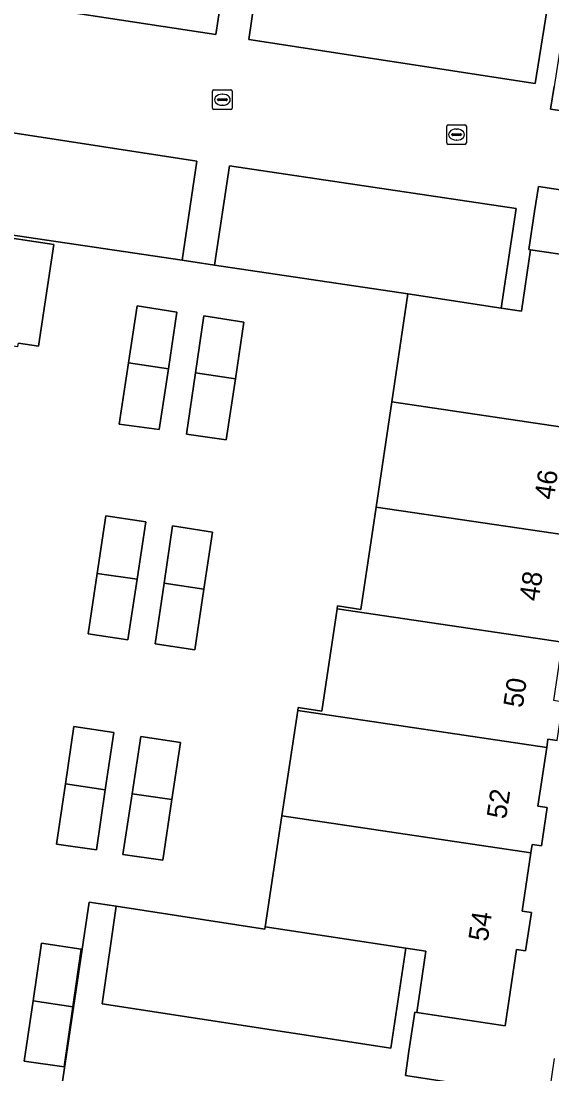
# Model space of a CAD drawing. Extents: x 164148 to 165261, y 382513 to 383432.
# Drawn here: x 164360 to 164386.9, y 382925.3 to 382978.7 of the extents above; entities that cross this region are included whole.
import ezdxf

# ---------------------------------------------------------------- set-up
doc = ezdxf.new("R2010")
doc.units = 0
for name, color, linetype in [('IMGEO_Erf', 7, 'Continuous'), ('IMGEO_Kolk', 7, 'Continuous'), ('IMGEO_Pand', 7, 'Continuous'), ('IMGEO_Pand_nummerreeks', 7, 'Continuous'), ('IMGEO_Parkeervlak_open', 7, 'Continuous'), ('IMGEO_Rijbaan_lokaal_open', 7, 'Continuous')]:
    doc.layers.add(name, color=color, linetype=linetype)

msp = doc.modelspace()

# ---------------------------------------------------------------- linework, layer by layer
at = {"layer": 'IMGEO_Erf'}
for points in [[(164392.466, 382980.616), (164391.885, 382976.741), (164387.391, 382977.422), (164387.359, 382977.427), (164387.033, 382975.364), (164386.852, 382974.222), (164394.057, 382973.175), (164398.318, 383001.938)], [(164393.467, 382969.194), (164386.248, 382970.282), (164386.051, 382969.013), (164385.759, 382967.092), (164385.848, 382967.079), (164390.338, 382966.42)], [(164358.298, 382967.859), (164361.68, 382967.348), (164360.899, 382962.187), (164359.88, 382962.335)], [(164361.351, 382919.771), (164363.474, 382933.973), (164364.842, 382933.776), (164372.377, 382932.608), (164372.394, 382932.721), (164373.238, 382938.355), (164374.038, 382943.697), (164374.061, 382943.851), (164375.257, 382943.667), (164376.031, 382948.861), (164376.053, 382949.005), (164377.241, 382948.828), (164378.014, 382954.022), (164378.809, 382959.364), (164379.624, 382964.842), (164369.817, 382966.301), (164368.18, 382966.545), (164358.321, 382968.013)], [(164387.199, 382942.18), (164386.727, 382942.253), (164386.664, 382941.829), (164386.219, 382938.852), (164386.687, 382938.775), (164386.39, 382936.832), (164385.928, 382936.908), (164385.865, 382936.486), (164385.421, 382933.514), (164385.888, 382933.446), (164385.59, 382931.503), (164385.131, 382931.573), (164384.551, 382927.693), (164380.072, 382928.372), (164379.973, 382928.387), (164379.674, 382926.423), (164379.499, 382925.189), (164386.768, 382924.065), (164387.061, 382926.045)]]:
    msp.add_lwpolyline(points, dxfattribs=at)
for points in [[(164364.994, 382958.226), (164365.463, 382961.338), (164365.9, 382964.242), (164367.918, 382963.916), (164367.484, 382961.04), (164367.019, 382957.953)], [(164369.287, 382963.723), (164371.304, 382963.408), (164370.879, 382960.538), (164370.418, 382957.431), (164368.397, 382957.729), (164368.858, 382960.837)], [(164366.338, 382953.271), (164365.898, 382950.361), (164365.433, 382947.29), (164363.412, 382947.596), (164363.875, 382950.659), (164364.317, 382953.577)], [(164367.265, 382950.158), (164367.697, 382953.069), (164369.715, 382952.755), (164369.286, 382949.859), (164368.83, 382946.783), (164366.81, 382947.09)], [(164364.709, 382942.589), (164364.283, 382939.68), (164363.835, 382936.624), (164361.814, 382936.92), (164362.263, 382939.979), (164362.689, 382942.885)], [(164368.099, 382942.072), (164367.664, 382939.179), (164367.202, 382936.106), (164365.181, 382936.398), (164365.643, 382939.478), (164366.078, 382942.375)], [(164363.066, 382931.596), (164362.64, 382928.668), (164362.197, 382925.618), (164360.174, 382925.912), (164360.619, 382928.967), (164361.045, 382931.89)]]:
    msp.add_lwpolyline(points, close=True, dxfattribs=at)
at = {"layer": 'IMGEO_Kolk'}
for p, q in [((164369.72, 382974.267), (164369.72, 382975.119)), ((164369.795, 382975.193), (164370.647, 382975.193)), ((164370.721, 382975.119), (164370.721, 382974.267)), ((164369.979, 382974.687), (164369.979, 382974.699)), ((164370.417, 382974.65), (164370.019, 382974.65)), ((164370.022, 382974.736), (164370.42, 382974.736)), ((164370.208, 382974.973), (164370.233, 382974.973)), ((164370.463, 382974.699), (164370.463, 382974.687)), ((164370.647, 382974.193), (164369.795, 382974.193)), ((164370.231, 382974.413), (164370.206, 382974.413)), ((164381.591, 382972.499), (164381.591, 382973.351)), ((164381.666, 382973.425), (164382.518, 382973.425)), ((164382.079, 382973.205), (164382.104, 382973.205)), ((164382.592, 382973.351), (164382.592, 382972.499)), ((164381.85, 382972.919), (164381.85, 382972.931)), ((164382.288, 382972.882), (164381.89, 382972.882)), ((164381.893, 382972.968), (164382.291, 382972.968)), ((164382.102, 382972.645), (164382.077, 382972.645)), ((164382.334, 382972.931), (164382.334, 382972.919)), ((164382.518, 382972.425), (164381.666, 382972.425))]:
    msp.add_line(p, q, dxfattribs=at)
for points in [[(164369.72, 382974.267), (164369.72, 382975.119)], [(164369.795, 382975.193), (164370.647, 382975.193)], [(164370.721, 382975.119), (164370.721, 382974.267)], [(164370.647, 382974.193), (164369.795, 382974.193)], [(164381.591, 382972.499), (164381.591, 382973.351)], [(164381.666, 382973.425), (164382.518, 382973.425)], [(164382.592, 382973.351), (164382.592, 382972.499)], [(164382.518, 382972.425), (164381.666, 382972.425)]]:
    msp.add_lwpolyline(points, dxfattribs=at)
for centre, radius, start, end in [((164369.797, 382975.117), 0.0765, 91.552, 178.448), ((164369.797, 382975.117), 0.0765, 91.552, 178.448), ((164370.645, 382975.117), 0.0765, 1.552, 88.448), ((164370.645, 382975.117), 0.0765, 1.552, 88.448), ((164370.019, 382974.696), 0.0403, 85.8775, 175.7526), ((164370.016, 382974.686), 0.0366, 178.938, 274.7102), ((164370.42, 382974.693), 0.043, 264.8664, 352.4533), ((164370.424, 382974.698), 0.0386, 1.7309, 96.639), ((164369.797, 382974.269), 0.0765, 181.552, 268.448), ((164369.797, 382974.269), 0.0765, 181.552, 268.448), ((164370.645, 382974.269), 0.0765, 271.552, 358.448), ((164370.645, 382974.269), 0.0765, 271.552, 358.448), ((164381.668, 382973.349), 0.0765, 91.552, 178.448), ((164381.668, 382973.349), 0.0765, 91.552, 178.448), ((164382.516, 382973.349), 0.0765, 1.552, 88.448), ((164382.516, 382973.349), 0.0765, 1.552, 88.448), ((164381.668, 382972.501), 0.0765, 181.552, 268.448), ((164381.668, 382972.501), 0.0765, 181.552, 268.448), ((164381.89, 382972.928), 0.0403, 85.8775, 175.7526), ((164381.887, 382972.918), 0.0366, 178.938, 274.7102), ((164382.291, 382972.925), 0.043, 264.8664, 352.4533), ((164382.295, 382972.93), 0.0386, 1.7309, 96.639), ((164382.516, 382972.501), 0.0765, 271.552, 358.448), ((164382.516, 382972.501), 0.0765, 271.552, 358.448)]:
    msp.add_arc(centre, radius, start, end, dxfattribs=at)
for centre, major_axis, ratio, start_param, end_param in [((164370.207, 382974.693), (-0.387, 0.002), 0.722429, 4.712389, 7.853982), ((164370.232, 382974.693), (-0.39, 0.002), 0.717154, 1.570796, 4.712389), ((164382.078, 382972.925), (-0.387, 0.002), 0.722429, 4.712389, 7.853982), ((164382.103, 382972.925), (-0.39, 0.002), 0.717154, 1.570796, 4.712389)]:
    msp.add_ellipse(centre, major_axis=major_axis, ratio=ratio, start_param=start_param, end_param=end_param, dxfattribs=at)
at = {"layer": 'IMGEO_Pand'}
for points in [[(164361.68, 382967.348), (164358.298, 382967.859), (164358.321, 382968.013), (164353.568, 382968.731), (164352.542, 382968.886), (164353.016, 382972.004), (164348.531, 382972.665), (164347.954, 382968.819), (164347.472, 382968.888), (164347.194, 382966.942), (164347.662, 382966.867), (164347.236, 382964.03), (164359.855, 382962.167), (164359.88, 382962.335), (164360.899, 382962.187)], [(164389.758, 382962.536), (164390.338, 382966.42), (164385.848, 382967.079), (164385.387, 382963.963), (164384.358, 382964.12), (164379.624, 382964.842), (164378.809, 382959.364), (164389.057, 382957.848), (164389.467, 382960.594), (164389.942, 382960.525), (164390.227, 382962.469)], [(164367.918, 382963.916), (164365.9, 382964.242), (164365.463, 382961.338), (164367.484, 382961.04)], [(164371.304, 382963.408), (164369.287, 382963.723), (164368.858, 382960.837), (164370.879, 382960.538)], [(164367.484, 382961.04), (164365.463, 382961.338), (164364.994, 382958.226), (164367.019, 382957.953)], [(164370.879, 382960.538), (164368.858, 382960.837), (164368.397, 382957.729), (164370.418, 382957.431)], [(164389.428, 382957.119), (164388.959, 382957.188), (164389.057, 382957.848), (164378.809, 382959.364), (164378.014, 382954.022), (164388.259, 382952.508), (164388.669, 382955.248), (164389.14, 382955.178)], [(164388.162, 382951.861), (164388.259, 382952.508), (164378.014, 382954.022), (164377.241, 382948.828), (164376.053, 382949.005), (164376.031, 382948.861), (164387.461, 382947.169), (164387.872, 382949.916), (164388.334, 382949.842), (164388.632, 382951.789)], [(164366.338, 382953.271), (164364.317, 382953.577), (164363.875, 382950.659), (164365.898, 382950.361)], [(164369.715, 382952.755), (164367.697, 382953.069), (164367.265, 382950.158), (164369.286, 382949.859)], [(164365.898, 382950.361), (164363.875, 382950.659), (164363.412, 382947.596), (164365.433, 382947.29)], [(164369.286, 382949.859), (164367.265, 382950.158), (164366.81, 382947.09), (164368.83, 382946.783)], [(164387.461, 382947.169), (164376.031, 382948.861), (164375.257, 382943.667), (164374.061, 382943.851), (164374.038, 382943.697), (164386.664, 382941.829), (164386.727, 382942.253), (164387.199, 382942.18), (164387.488, 382944.128), (164387.018, 382944.201)], [(164386.664, 382941.829), (164374.038, 382943.697), (164373.238, 382938.355), (164385.865, 382936.486), (164385.928, 382936.908), (164386.39, 382936.832), (164386.687, 382938.775), (164386.219, 382938.852)], [(164364.709, 382942.589), (164362.689, 382942.885), (164362.263, 382939.979), (164364.283, 382939.68)], [(164368.099, 382942.072), (164366.078, 382942.375), (164365.643, 382939.478), (164367.664, 382939.179)], [(164364.283, 382939.68), (164362.263, 382939.979), (164361.814, 382936.92), (164363.835, 382936.624)], [(164367.664, 382939.179), (164365.643, 382939.478), (164365.181, 382936.398), (164367.202, 382936.106)], [(164385.865, 382936.486), (164373.238, 382938.355), (164372.394, 382932.721), (164379.522, 382931.636), (164380.527, 382931.483), (164380.072, 382928.372), (164384.551, 382927.693), (164385.131, 382931.573), (164385.59, 382931.503), (164385.888, 382933.446), (164385.421, 382933.514)], [(164363.066, 382931.596), (164361.045, 382931.89), (164360.619, 382928.967), (164362.64, 382928.668)], [(164362.64, 382928.668), (164360.619, 382928.967), (164360.174, 382925.912), (164362.197, 382925.618)]]:
    msp.add_lwpolyline(points, close=True, dxfattribs=at)
at = {"layer": 'IMGEO_Parkeervlak_open'}
for points in [[(164370.665, 382983.122), (164363.162, 382984.247), (164356.043, 382985.302), (164355.296, 382980.243), (164369.885, 382978)], [(164386.899, 382980.686), (164380.908, 382981.585), (164372.3, 382982.876), (164371.569, 382977.741), (164386.081, 382975.51)], [(164354.32, 382973.818), (164353.568, 382968.731), (164358.321, 382968.013), (164368.18, 382966.545), (164368.925, 382971.573)], [(164370.583, 382971.338), (164369.817, 382966.301), (164379.624, 382964.842), (164384.358, 382964.12), (164385.122, 382969.166)], [(164379.522, 382931.636), (164372.394, 382932.721), (164372.377, 382932.608), (164364.842, 382933.776), (164364.119, 382928.814), (164378.755, 382926.565)]]:
    msp.add_lwpolyline(points, close=True, dxfattribs=at)
at = {"layer": 'IMGEO_Rijbaan_lokaal_open'}
for points in [[(164370.665, 382983.122), (164369.885, 382978), (164355.296, 382980.243)], [(164386.899, 382980.686), (164386.081, 382975.51), (164371.569, 382977.741), (164372.3, 382982.876)], [(164346.897, 382980.236), (164346.307, 382976.27), (164353.607, 382975.217), (164353.387, 382973.962), (164353.424, 382973.956), (164353.125, 382971.987), (164353.016, 382972.004), (164352.542, 382968.886), (164353.568, 382968.731), (164354.32, 382973.818), (164368.925, 382971.573), (164368.18, 382966.545), (164369.817, 382966.301), (164370.583, 382971.338), (164385.122, 382969.166), (164384.358, 382964.12), (164385.387, 382963.963), (164385.848, 382967.079), (164385.759, 382967.092), (164386.051, 382969.013), (164386.248, 382970.282), (164393.467, 382969.194)], [(164394.057, 382973.175), (164386.852, 382974.222), (164387.033, 382975.364)]]:
    msp.add_lwpolyline(points, dxfattribs=at)
msp.add_lwpolyline([(164379.674, 382926.423), (164379.973, 382928.387), (164380.072, 382928.372), (164380.527, 382931.483), (164379.522, 382931.636), (164378.755, 382926.565), (164364.119, 382928.814), (164364.842, 382933.776), (164363.474, 382933.973), (164361.351, 382919.771), (164361.014, 382917.516), (164362.394, 382917.305), (164363.127, 382922.256), (164377.768, 382920.053), (164377.017, 382915.072), (164378.064, 382914.912), (164378.531, 382918.027), (164378.422, 382918.043), (164378.704, 382919.912), (164378.902, 382921.233), (164386.181, 382920.095), (164386.768, 382924.065), (164379.499, 382925.189)], close=True, dxfattribs=at)

# ---------------------------------------------------------------- texts
at = {"layer": 'IMGEO_Pand_nummerreeks'}
for s, rotation, p in [('46', 81.4861, (164387.02, 382954.363)), ('48', 81.5032, (164386.25, 382949.213)), ('50', 81.5032, (164385.442, 382943.804)), ('52', 81.5032, (164384.599, 382938.162)), ('54', 81.4975, (164383.67, 382931.945))]:
    msp.add_text(s, height=1, rotation=rotation, dxfattribs=at).set_placement(p)

doc.saveas('drawing.dxf')
